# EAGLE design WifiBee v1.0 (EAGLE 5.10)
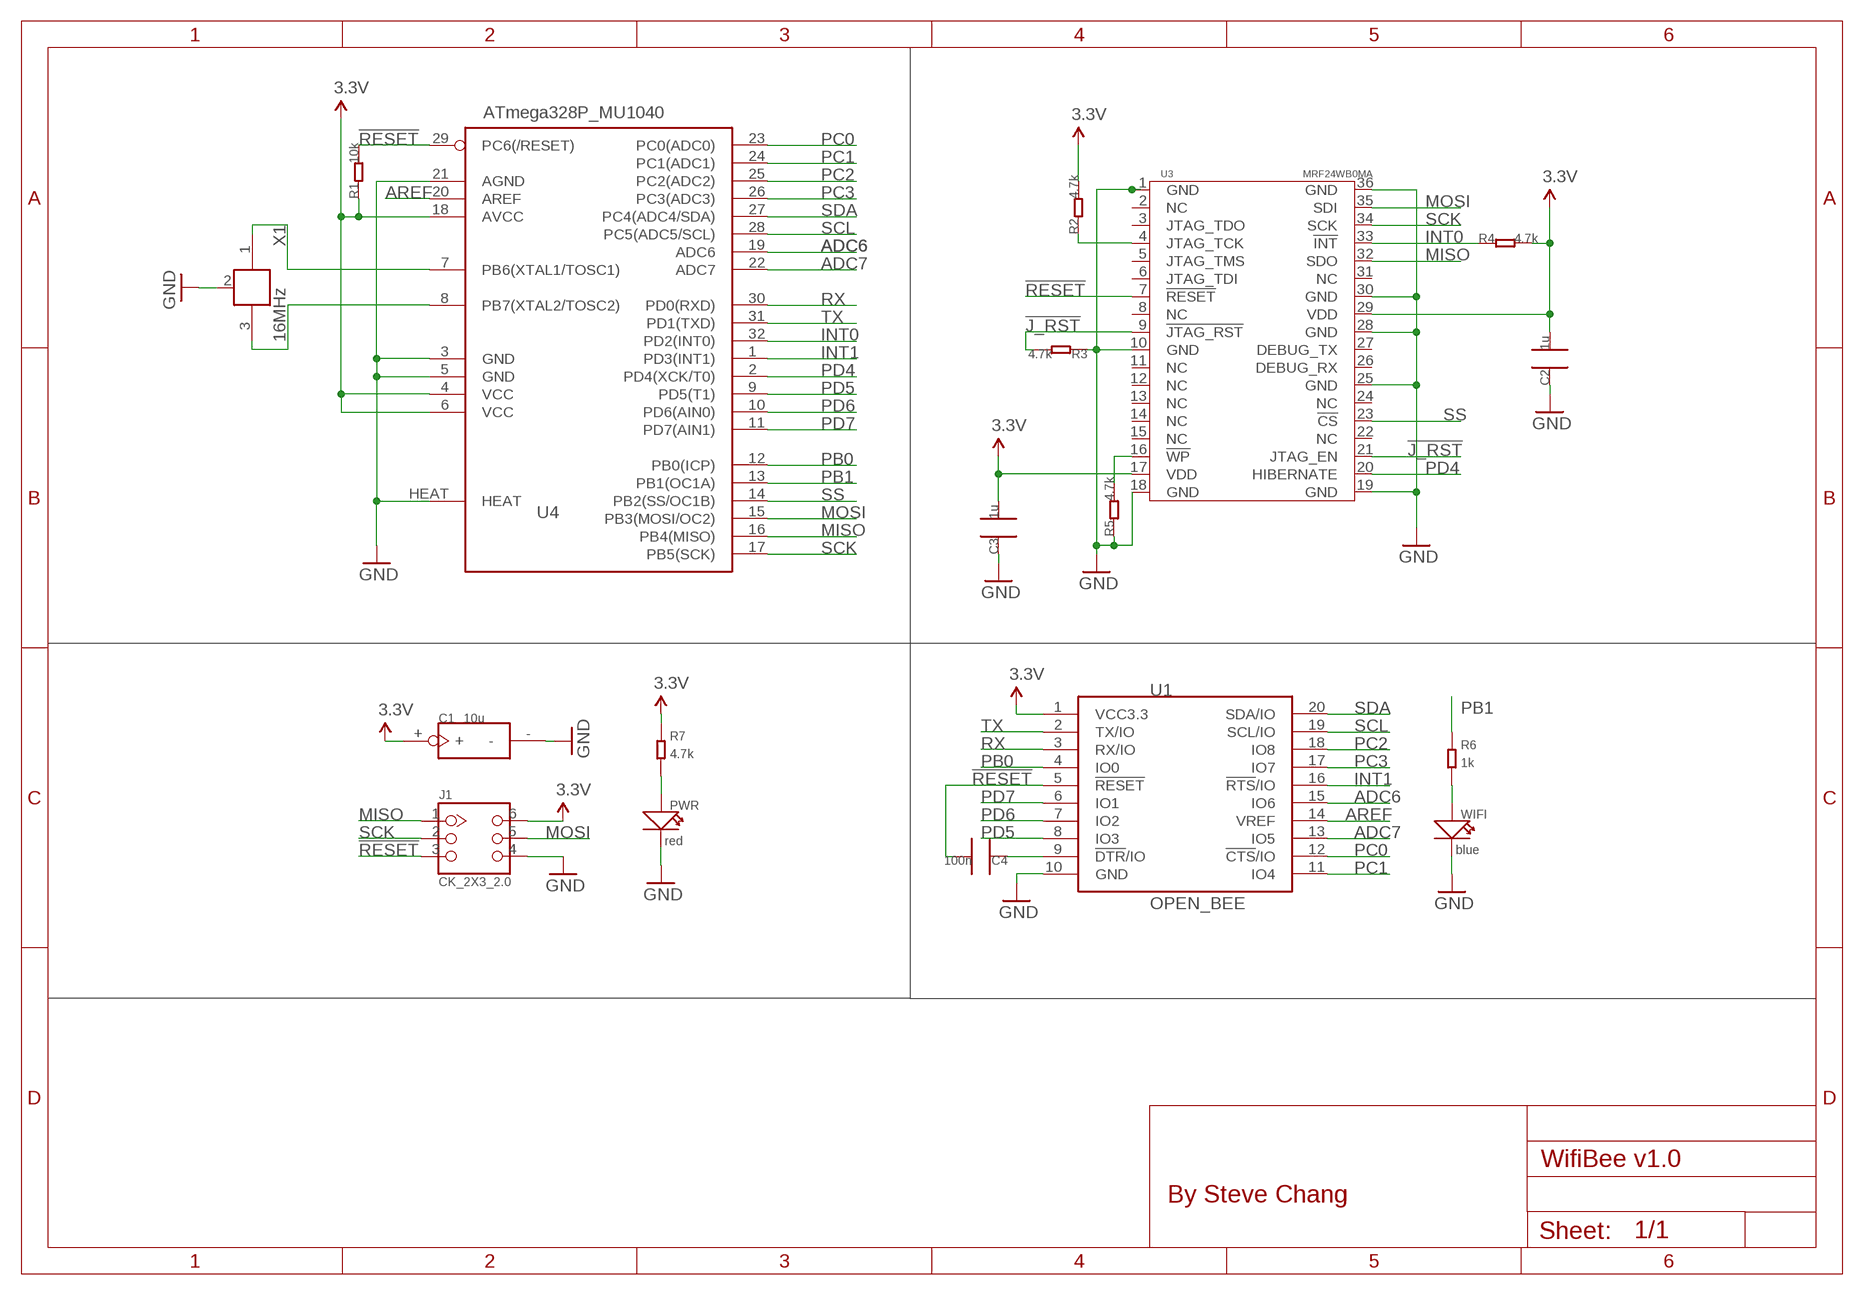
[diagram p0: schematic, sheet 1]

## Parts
C1  10u  C_TAN_B  [C_TAN_3X3.5]
C2  1u  C0603  [0603]
C3  1u  C0603  [0603]
C4  100n  C0603  [0603]
J1  CK_2X3_2.0  [CK_2X3_2.0]
PWR  red  LED0603_DD  [LED0603]
R1  10k  R0603  [0603]
R2  4.7k  R0603  [0603]
R3  4.7k  R0603  [0603]
R4  4.7k  R0603  [0603]
R5  4.7k  R0603  [0603]
R6  1k  R0603  [0603]
R7  4.7k  R0603  [0603]
U1  OPEN_BEE  OPEN_BEE_SMD  [XBEE_EXT_SMD]
U3  MRF24WB0MA  WIFI_SMT  [MRF24WB0MA]
U4  ATmega328P_MU1040  MEGA8_MLF32X  [MLF32X]
WIFI  blue  LED0603_DD  [LED0603]
X1  16MHz  XTAL_NCVER  [XTAL_3X2]

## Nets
3.3V: C1.+ C2.2 C3.2 J1.6 R1.1 R2.2 R4.2 R7.1 U1.1(VCC3.3) U3.17(VDD) U3.29(VDD) U4.4(VCC) U4.6(VCC) U4.18(AVCC)
!J_RST: R3.2 U3.9(!JTAG_RST) U3.21(JTAG_EN)
!RESET: C4.2 J1.3 R1.2 U1.5(!RESET) U3.7(!RESET) U4.29(PC6(/RESET))
ADC6: U1.15(IO6) U4.19(ADC6)
ADC7: U1.13(IO5) U4.22(ADC7)
AREF: U1.14(VREF) U4.20(AREF)
GND: C1.- C2.1 C3.1 J1.4 PWR.2(-) R3.1 R5.1 U1.10(GND) U3.1(GND) U3.10(GND) U3.18(GND) U3.19(GND) U3.25(GND) U3.28(GND) U3.30(GND) U3.36(GND) U4.3(GND) U4.5(GND) U4.21(AGND) U4.HEAT WIFI.2(-) X1.2(GND)
INT0: R4.1 U3.33(!INT) U4.32(PD2(INT0))
INT1: U1.16(!RTS!/IO) U4.1(PD3(INT1))
MISO: J1.1 U3.32(SDO) U4.16(PB4(MISO))
MOSI: J1.5 U3.35(SDI) U4.15(PB3(MOSI/OC2))
N$1: C4.1 U1.9(!DTR!/IO)
N$3: R5.2 U3.16(!WP)
N$5: R2.1 U3.4(JTAG_TCK)
N$7: R6.2 WIFI.1(+)
N$8: PWR.1(+) R7.2
N$11: U4.7(PB6(XTAL1/TOSC1)) X1.1
N$13: U4.8(PB7(XTAL2/TOSC2)) X1.3
PB0: U1.4(IO0) U4.12(PB0(ICP))
PB1: R6.1 U4.13(PB1(OC1A))
PC0: U1.12(!CTS!/IO) U4.23(PC0(ADC0))
PC1: U1.11(IO4) U4.24(PC1(ADC1))
PC2: U1.18(IO8) U4.25(PC2(ADC2))
PC3: U1.17(IO7) U4.26(PC3(ADC3))
PD4: U3.20(HIBERNATE) U4.2(PD4(XCK/T0))
PD5: U1.8(IO3) U4.9(PD5(T1))
PD6: U1.7(IO2) U4.10(PD6(AIN0))
PD7: U1.6(IO1) U4.11(PD7(AIN1))
RX: U1.3(RX/IO) U4.30(PD0(RXD))
SCK: J1.2 U3.34(SCK) U4.17(PB5(SCK))
SCL: U1.19(SCL/IO) U4.28(PC5(ADC5/SCL))
SDA: U1.20(SDA/IO) U4.27(PC4(ADC4/SDA))
SS: U3.23(!CS) U4.14(PB2(SS/OC1B))
TX: U1.2(TX/IO) U4.31(PD1(TXD))
Unconnected: U3.2(NC) U3.3(JTAG_TDO) U3.5(JTAG_TMS) U3.6(JTAG_TDI) U3.8(NC) U3.11(NC) U3.12(NC) U3.13(NC) U3.14(NC) U3.15(NC) U3.22(NC) U3.24(NC) U3.26(DEBUG_RX) U3.27(DEBUG_TX) U3.31(NC)

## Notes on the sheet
- By Steve Chang

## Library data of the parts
C1 = CPT_SMD:C_TAN
C2-C4 = CPT_SMD:C0603; C0603: 100N
J1 = CONNECTER:CK_2X3
PWR WIFI = CPT_SMD:LED0603
R1-R7 = CPT_SMD:R0603
U1 = EXT_moudle:OPEN_BEE
U3 = EXT_moudle:WIFI
U4 = ICs_v54:MEGA8
X1 = CPT_SMD:XTAL_NC

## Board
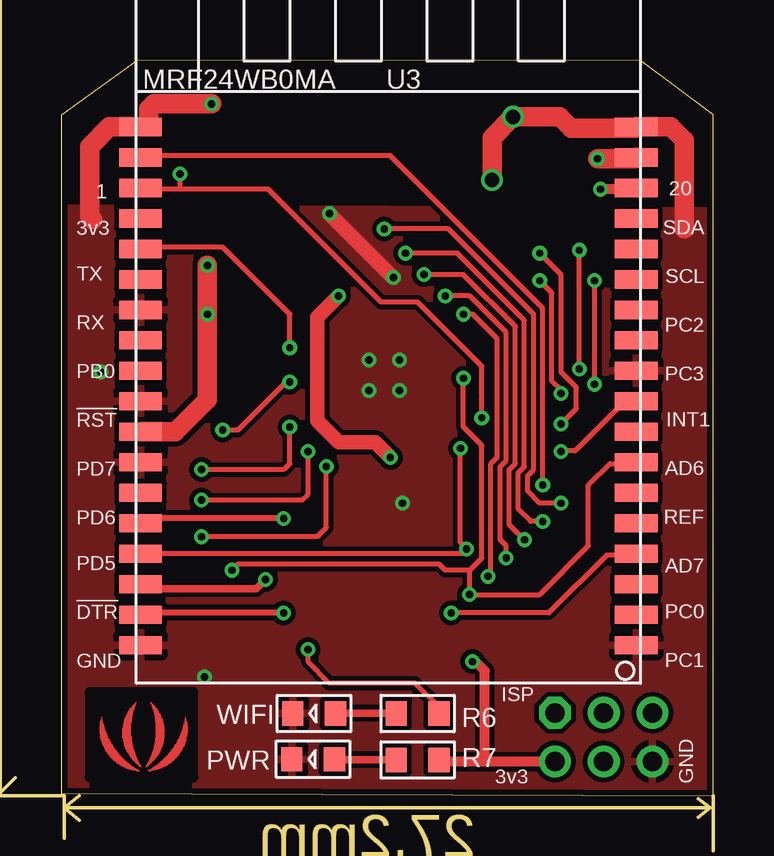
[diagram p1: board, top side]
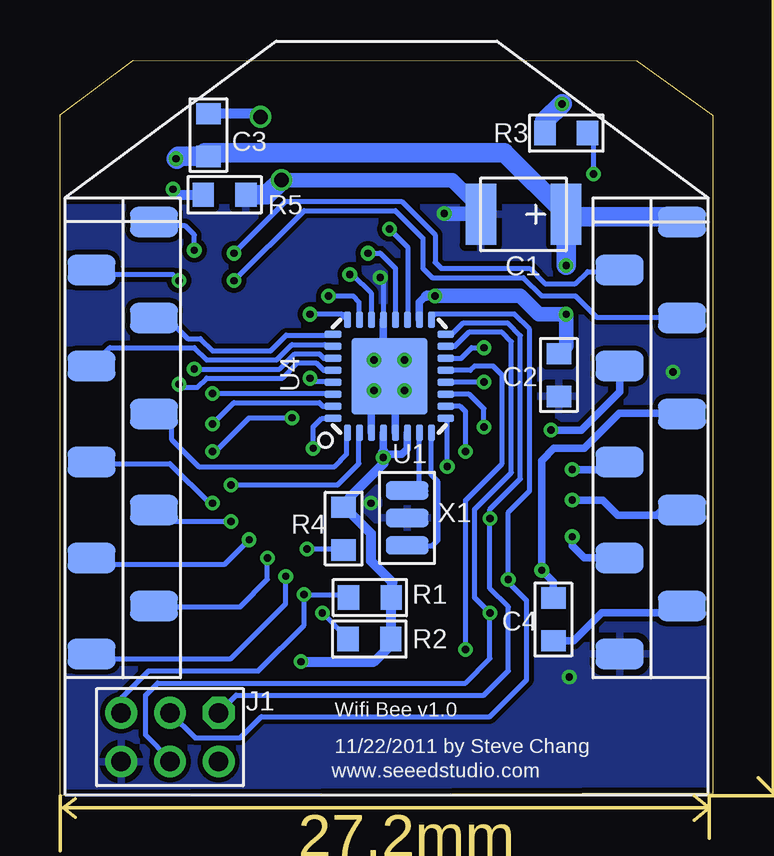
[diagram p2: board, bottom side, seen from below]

Size 27.18 x 30.66 mm. Coordinates in mm from the lower left corner, seen from the top.
Outline: 24.14,30.66 27.18,28.37 27.18,0 0,0.1 0,28.35 3.15,30.63 3.15,30.63 24.14,30.66
Outline: 24.14,30.66 24.14,30.66
Copper layers (1*16): Top 0.035mm / dielectric 1.5mm / Bottom 0.035mm
Design rules "SeeedStudio_rule_no_angle_090911": minimum track width 6mil, minimum drill 12mil, track to track 6mil, track to pad 6mil, pad to pad 6mil, via to via 6mil, smd to smd 0mil, copper to edge 10mil, drill to drill 10mil, minimum pad ring 10mil, minimum via ring 6mil, stop-mask expansion 2mil, vias tented up to drill 100mil, thermal gap 10mil
tRestrict: area 1.2,0.8 to 5.5,4.3
Milling: 26 lines

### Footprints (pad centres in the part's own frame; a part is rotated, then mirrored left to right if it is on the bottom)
C_TAN_3X3.5 = smd 2.54 x 1.27: + 0,1.778; - 0,-1.778
0603 = smd 0.889 x 1.016: 1 -0.889,0; 2 0.889,0
CK_2X3_2.0 = drill 0.813 pad 1.27 octagon: 1 -1.016,2.032 | drill 0.813 pad 1.27 round: 2 -1.016,0; 3 -1.016,-2.032; 4 1.016,-2.032; 5 1.016,0; 6 1.016,2.032
LED0603 = smd 0.889 x 1.016: 1 -0.889,0; 2 0.889,0
XBEE_EXT_SMD = smd 2 x 1.27: 1 12.3,9; 2 9.7,7; 3 12.3,5; 4 9.7,3; 5 12.3,1; 6 9.7,-1; 7 12.3,-3; 8 9.7,-5; 9 12.3,-7; 10 9.7,-9; 11 -12.3,-9; 12 -9.7,-7; 13 -12.3,-5; 14 -9.7,-3; 15 -12.3,-1; 16 -9.7,1; 17 -12.3,3; 18 -9.7,5; 19 -12.3,7; 20 -9.7,9
MRF24WB0MA = smd 1.778 x 0.762: 1 -10.624,23.695; 2 -10.624,22.425; 3 -10.624,21.155; 4 -10.624,19.885; 5 -10.624,18.615; 6 -10.624,17.345; 7 -10.624,16.075; 8 -10.624,14.805; 9 -10.624,13.535; 10 -10.624,12.265; 11 -10.624,10.995; 12 -10.624,9.725; 13 -10.624,8.455; 14 -10.624,7.185; 15 -10.624,5.915; 16 -10.624,4.645; 17 -10.624,3.375; 18 -10.624,2.105; 19 10.034,2.105; 20 10.034,3.375; 21 10.034,4.645; 22 10.034,5.915; 23 10.034,7.185; 24 10.034,8.455; 25 10.034,9.725; 26 10.034,10.995; 27 10.034,12.265; 28 10.034,13.535; 29 10.034,14.805; 30 10.034,16.075; 31 10.034,17.345; 32 10.034,18.615; 33 10.034,19.885; 34 10.034,21.155; 35 10.034,22.425; 36 10.034,23.695
MLF32X = smd 0.7 x 0.3: 1 -2.35,1.75; 2 -2.35,1.25; 3 -2.35,0.75; 4 -2.35,0.25; 5 -2.35,-0.25; 6 -2.35,-0.75; 7 -2.35,-1.25; 8 -2.35,-1.75; 17 2.35,-1.75; 18 2.35,-1.25; 19 2.35,-0.75; 20 2.35,-0.25; 21 2.35,0.25; 22 2.35,0.75; 23 2.35,1.25; 24 2.35,1.75 | smd 0.3 x 0.7: 9 -1.75,-2.35; 10 -1.25,-2.35; 11 -0.75,-2.35; 12 -0.25,-2.35; 13 0.25,-2.35; 14 0.75,-2.35; 15 1.25,-2.35; 16 1.75,-2.35; 25 1.75,2.35; 26 1.25,2.35; 27 0.75,2.35; 28 0.25,2.35; 29 -0.25,2.35; 30 -0.75,2.35; 31 -1.25,2.35; 32 -1.75,2.35 | smd 3.175 x 3.175: HEAT 0,0
XTAL_3X2 = smd 0.762 x 1.778: 1 -1.143,0; 2 0,0; 3 1.143,0

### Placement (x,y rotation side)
C1  7.88,24.23 270 bottom
C2  6.41,17.53 90 bottom
C3  21.01,27.53 270 bottom
C4  6.63,7.35 90 bottom
J1  22.61,2.44 270 bottom
PWR  10.5,1.52 180 top
R1  14.28,8.26 180 bottom
R2  14.3,6.53 0 bottom
R3  6.1,27.61 0 bottom
R4  15.37,11.13 90 bottom
R5  20.33,25.04 180 bottom
R6  14.86,3.43 180 top
R7  14.86,1.5 180 top
U1  13.57,14.91 0 bottom
U3  13.35,29.97 180 top
U4  13.47,17.48 90 bottom
U$1  [LOGO_COPPER_150X124]  3.43,2.16 0 top
WIFI  10.54,3.43 180 top
X1  12.73,11.58 270 bottom

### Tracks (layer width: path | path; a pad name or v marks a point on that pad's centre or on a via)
3.3V  (via drill 0.3)
  Top 0.305: 15.82,1.43 R7.1
  Top 0.406: v17.15,5.59 17.28,5.59 17.66,5.21 17.66,1.68 | 17.91,1.43 17.66,1.68 | J1.6 17.91,1.43 | 17.91,1.43 15.82,1.43 | 17.66,1.68 17.66,1.65 17.45,1.45
  Top 0.61: v11.56,20.83 10.67,19.94 10.67,15.62 11.56,14.73 13.09,14.73 v13.72,14.1
  Top 0.813: v22.36,26.54 23.92,26.54 U3.17 | v6.1,22.1 v6.1,20.07 6.1,16.51 4.75,15.16 U3.29
  Bottom 0.305: 11.94,20.83 12.22,20.55 U4.18 | U4.6 12.72,14.47 12.96,14.22 13.59,14.22 13.72,14.35 U4.4
  Bottom 0.406: v11.56,20.83 11.94,20.83 | 13.72,14.35 v13.72,14.1 13.72,13.84 15.12,12.45 15.12,12.27 R4.2 15.33,12.02 14.23,10.92 14.23,9.78 13.34,8.89 13.34,8.31 R1.1 13.39,6.55 R2.2 13.41,6.28 14.1,5.59 v17.15,5.59
  Bottom 0.61: v11.56,20.83 8.01,20.83 7.24,20.07 v6.1,20.07 6.1,18.73 C2.2
  Bottom 0.813: 22.33,26.51 v22.36,26.54 22.26,26.64 C3.2 21.17,26.8 8.67,26.8 C1.+ | C1.+ 6,24.13 1.5,24.13 U1.1 | v6.1,22.1 C1.+
!J_RST  (via drill 0.3)
  Top 0.152: U3.9 23.77,16.64 | 3.37,25.27 U3.21
  Top 0.203: v17.53,15.75 17.53,17.91 14.86,20.57 13.34,20.57 8.64,25.27 4.83,25.27 | 4.83,25.27 3.37,25.27 | v4.96,25.91 4.96,25.4 4.83,25.27 | U3.9 23.48,16.44 21.42,14.38 20.86,14.38 v20.83,14.35
  Bottom 0.152: 4.96,27.36 R3.2
  Bottom 0.203: v17.53,15.75 19.31,15.75 20.71,14.35 v20.83,14.35 | v4.96,25.91 4.96,27.36
!RESET  (via drill 0.3)
  Top 0.152: 23.92,13.84 U3.7
  Top 0.203: 23.92,13.84 22.86,13.84 21.98,12.95 21.98,10.41 19.94,8.38 v17.02,8.38 17.02,9.4 | v16.77,17.4 16.77,15.37 17.53,14.61 17.53,9.91 17.02,9.4 | v7.12,9.4 7.37,9.65 15.75,9.65 16.01,9.4 17.02,9.4
  Bottom 0.152: 15.86,17.27 U4.29 | 15.3,8.38 R1.2
  Bottom 0.203: 15.86,17.27 16.64,17.27 v16.77,17.4 | J1.3 24.64,4.06 23.5,5.21 18.93,5.21 17.02,7.11 v17.02,8.38 15.3,8.38
  Bottom 0.305: C4.2 6.63,8.91 v7.12,9.4 7.12,13.97 6.61,14.48 5.34,14.48 3.88,15.93 1.3,15.93 U1.5
ADC6  (via drill 0.3)
  Top 0.203: v20.83,12.19 19.94,12.19 19.44,12.7 19.44,13.34 19.69,13.59 19.69,20.07 16.13,23.62 v13.47,23.62
  Bottom 0.152: U1.15 25.81,13.84
  Bottom 0.203: v20.83,12.19 20.96,12.19 22.61,13.84 25.81,13.84 | v13.47,23.62 12.71,22.86 12.71,19.84
  Bottom 0.254: 12.71,19.84 U4.19
ADC7  (via drill 0.3)
  Top 0.203: v19.31,10.67 18.67,11.3 18.67,13.59 18.93,13.84 18.93,19.56 16.77,21.72 v15.12,21.72
  Bottom 0.152: 14.23,19.84 U4.22
  Bottom 0.203: v15.12,21.72 14.99,21.72 14.23,20.95 14.23,19.84 | v19.31,10.67 20.32,9.65 25.64,9.65 25.64,9.67 U1.13
AREF  (via drill 0.3)
  Top 0.203: v20.07,11.43 19.56,11.43 19.05,11.94 19.05,13.46 19.31,13.72 19.31,19.81 16.52,22.61 v14.36,22.61
  Bottom 0.152: U4.20
  Bottom 0.203: 22.8,11.43 23.38,11.43 | v14.36,22.61 13.85,22.61 13.21,21.97 U4.20 | 22.8,11.43 v20.07,11.43 | U1.14 22.8,11.43
GND  (via drill 0.3, 0.6)
  Top 0.406: 3.66,27.87 U3.19
  Top 0.61: v11.18,24.26 v13.85,21.59
  Top 0.813: 1.32,24 1.19,24.13 1.19,27.05 2.01,27.87 3.66,27.87 3.66,28.63 3.86,28.83 v6.27,28.83 | 25.96,23.62 25.96,27.3 25.4,27.87 U3.18 23.92,27.81 21.26,27.81 20.78,28.29 v18.83,28.29 17.96,27.42 v17.96,25.65
  Bottom 0.152: 9.94,24.51 C1.-
  Bottom 0.203: U4.21 13.72,21.46 v13.85,21.59
  Bottom 0.305: U4.21 13.72,18.8 | 13.72,18.8 13.59,18.67 | U4.5 13.22,17.23 U4.HEAT | U4.3 14.22,16.73 U4.HEAT | U4.HEAT 13.47,17.78 | v14.1,16.89 14.06,16.89 U4.HEAT | 13.72,18.8 13.72,17.73 U4.HEAT
  Bottom 0.406: C3.1 18.96,28.42 v18.83,28.29
  Bottom 0.61: v11.18,24.26 9.69,24.26 C1.- | 9.94,24.51 9.94,24.75 10.85,25.65 v17.96,25.65
  Bottom 0.813: R3.1 6.99,28.12 v6.27,28.83 | R5.1 18.57,25.04 v17.96,25.65
  other vias: 14.1,18.16 5.97,4.95 14.23,12.19 1.66,17.65 12.83,18.16 12.83,16.89
  pour Top (isolate 0.203): 26.93,24.38 0.39,24.51 0.39,0.13 26.93,0
  pour Bottom (isolate 0.203): 26.93,24.51 0.39,24.51 0.39,0.13 26.93,0.13
INT0  (via drill 0.3)
  Top 0.203: v16.64,14.48 16.64,10.54 v16.9,10.29 16.7,10.09 U3.33
  Bottom 0.152: 15.42,10.29 R4.1
  Bottom 0.203: U4.32 16.28,15.73 16.64,15.37 v16.64,14.48 | v16.9,10.29 15.42,10.29
INT1
  Bottom 0.152: 15.24,15.1 U4.1
  Bottom 0.203: 15.24,15.1 15.24,14.22 15.75,13.72 21.42,13.72 22.54,14.83 22.54,15.75 22.61,15.82 23.19,15.82 U1.16
MISO  (via drill 0.3)
  Top 0.254: 3.38,11.43 U3.32 3.51,11.56 v9.28,11.56
  Bottom 0.203: U4.16 10.86,19.24 10.42,19.68 8.51,19.68 8.01,19.18 8.01,13.21 9.28,11.94 v9.28,11.56 9.28,8.64 8.51,7.87 8.51,5.21 9.53,4.19 19.85,4.19 J1.1
  Bottom 0.254: U4.16
MOSI  (via drill 0.3)
  Top 0.254: v9.28,7.62 3.38,7.62 U3.35
  Bottom 0.203: U4.15 10.74,18.73 10.16,19.3 8.77,19.3 8.39,18.92 8.39,13.46 9.91,11.94 9.91,8.26 v9.28,7.62 9.28,5.71 10.29,4.7 23.12,4.7 23.63,4.19 23.63,2.54 22.61,1.52 J1.5
N$1
  Bottom 0.305: C4.1 5.79,6.46 4.62,7.62 1.56,7.62 U1.9
N$3  (via drill 0.3)
  Top 0.406: v22.48,25.27 23.92,25.27 U3.16
  Bottom 0.406: R5.2 22.26,25.04 v22.48,25.27
N$5  (via drill 0.3)
  Top 0.152: U3.4 23.92,10.03
  Top 0.203: v16.26,7.62 20.32,7.62 22.74,10.03 23.92,10.03
  Bottom 0.203: v16.26,7.62 15.3,6.66 15.3,6.63 R2.1
N$7
  Top 0.305: R6.2 WIFI.1
N$8
  Top 0.305: R7.2 11.41,1.5 PWR.1
N$11
  Bottom 0.203: U4.7 12.22,12.97 11.94,12.7 12.71,12.7 X1.1
N$13
  Bottom 0.152: X1.3 12.71,10.41
  Bottom 0.203: U4.8 11.72,13.36 11.44,13.08 11.44,10.67 11.69,10.41 12.71,10.41
PB0  (via drill 0.3)
  Top 0.203: v9.53,17.25 9.38,17.25 7.37,15.24 v6.74,15.24
  Bottom 0.152: U4.12 11.1,17.25
  Bottom 0.203: 11.1,17.25 v9.53,17.25
  Bottom 0.305: v6.74,15.24 5.47,15.24 3.87,16.84 U1.4
PB1  (via drill 0.3)
  Top 0.152: R6.1 15.75,3.68
  Top 0.203: 15.75,3.68 14.74,4.7 11.18,4.7 10.29,5.59 v10.29,6.1
  Top 0.254: R6.1
  Bottom 0.203: U4.13 10.09,17.73 9.91,17.91 9.15,17.91 8.77,17.53 8.77,13.84 10.29,12.32 v10.29,6.1
PC0  (via drill 0.3)
  Top 0.203: v18.55,9.91 18.55,10.41 18.29,10.67 18.29,13.72 18.55,13.97 18.55,19.3 17.02,20.83 v16.01,20.83
  Bottom 0.152: U1.12 23.24,7.87
  Bottom 0.203: v16.01,20.83 14.99,20.83 14.74,20.57 14.74,19.85 | v18.55,9.91 18.55,9.02 19.69,7.87 23.24,7.87
  Bottom 0.254: 14.74,19.85 U4.23
PC1  (via drill 0.3)
  Top 0.203: v17.79,9.14 17.91,9.27 17.91,13.84 18.17,14.1 18.17,19.05 17.15,20.07 v16.77,20.07
  Bottom 0.152: v16.77,20.07 15.45,20.07
  Bottom 0.203: v17.79,9.14 17.79,8 20.07,5.71 25.68,5.71 U1.11 | 15.45,20.07 16.8,20.07 | 15.45,20.07 U4.24 | 15.45,20.07 15.22,20.07 15.17,20.02
PC2
  Bottom 0.152: 15.85,19.2 U4.25
  Bottom 0.203: 15.85,19.2 17.77,19.2 18.42,18.54 20.83,18.54 21.34,19.05 21.88,19.05 22.73,19.91 U1.18
PC3
  Bottom 0.203: U4.26 16.09,18.73 16.16,18.8 17.53,18.8 18.17,18.16 21.09,18.16 21.59,18.67 25.11,18.67 U1.17
PD4  (via drill 0.3)
  Top 0.152: 3.38,26.67 U3.20
  Top 0.203: v20.07,12.95 20.07,20.32 13.72,26.67 3.38,26.67
  Bottom 0.152: 14.74,15.11 U4.2
  Bottom 0.203: 14.74,15.11 14.74,13.84 15.63,12.95 v20.07,12.95
PD5  (via drill 0.3)
  Top 0.203: v11.05,13.72 11.05,11.18 10.67,10.79 v5.85,10.79
  Bottom 0.152: 11.05,15.67 U4.9
  Bottom 0.203: v11.05,13.72 11.05,15.67
  Bottom 0.305: U1.8 5.34,9.91 5.85,10.41 v5.85,10.79
PD6  (via drill 0.3)
  Top 0.203: v10.29,14.35 10.29,12.57 10.04,12.32 v5.85,12.32
  Bottom 0.203: U4.10 10.52,16.23 10.29,16 v10.29,14.35
  Bottom 0.254: 2,12.06 2.38,11.68
  Bottom 0.305: v5.85,12.32 4.58,12.32 3.94,11.68 1.62,11.68 | U1.7 1.5,11.68 1.62,11.68 | 1.62,11.68 2,12.06
PD7  (via drill 0.3)
  Top 0.203: v9.53,15.37 9.53,13.84 9.28,13.59 v5.85,13.59
  Bottom 0.203: U4.11 10.13,16.73 9.53,16.13 v9.53,15.37
  Bottom 0.305: v5.85,13.59 3.73,13.59 3.73,13.77 U1.6
RX  (via drill 0.3, 0.3 pad 0.61)
  Top 0.203: v20.83,16.76 20.83,16.89 20.45,17.27 20.45,20.95 v19.94,21.46
  Bottom 0.152: 15.85,16.76 U4.30 | 1.3,19.93 U1.3
  Bottom 0.203: v20.83,16.76 15.85,16.76 | v19.94,21.46 17.02,24.38 13.21,24.38 12.07,23.24 12.07,21.97 11.69,21.59 7.88,21.59 7.12,20.83 5.72,20.83 4.83,19.93 1.3,19.93
SCK  (via drill 0.3)
  Top 0.305: 3.51,9.02 U3.34 3.49,8.64 8.13,8.64 v8.51,9.02
  Bottom 0.203: 11.72,19.91 11.56,20.07 8.26,20.07 7.62,19.43 7.62,12.7 8.51,11.81 v8.51,9.02 8.51,8.89 7.75,8.13 7.75,4.83 9.28,3.3 18.8,3.3 19.69,2.41 21.57,2.41 J1.2
  Bottom 0.254: 11.72,19.91 U4.17
SCL  (via drill 0.3)
  Top 0.203: v22.23,17.14 v22.23,21.46
  Bottom 0.203: U4.28 16.21,17.73 16.52,18.03 17.28,18.03 17.91,17.4 21.09,17.4 21.47,17.02 22.1,17.02 v22.23,17.14 | v22.23,21.46 22.48,21.72 25.68,21.72 U1.19
SDA  (via drill 0.3)
  Top 0.203: v21.59,17.78 v21.59,22.73
  Bottom 0.203: U4.27 16.2,18.23 16.39,18.41 17.4,18.41 18.04,17.78 v21.59,17.78 | v21.59,22.73 21.59,23.37 21.98,23.75 23.37,23.75 | 23.37,23.75 23.61,23.75 | U1.20 23.27,23.85 23.37,23.75
SS  (via drill 0.3)
  Top 0.203: 3.38,22.86 6.74,22.86 9.53,20.07 v9.53,18.67
  Top 0.254: 3.38,22.86 U3.23
  Bottom 0.203: U4.14 10.48,18.23 10.04,18.67 v9.53,18.67
TX  (via drill 0.3, 0.3 pad 0.61)
  Top 0.203: v19.94,22.61 20.83,21.72 20.83,17.65 21.47,17.02 21.47,16.13 v20.83,15.49
  Bottom 0.152: 3.94,21.84 U1.2
  Bottom 0.203: U4.31 16.24,16.23 16.39,16.38 19.94,16.38 v20.83,15.49 | v19.94,22.61 17.79,24.77 12.96,24.77 11.56,23.37 11.56,22.23 11.31,21.97 7.62,21.97 6.99,21.34 5.72,21.34 5.21,21.84 3.94,21.84

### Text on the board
tPlace: 1 | 20 | SDA | 3v3 | SCL | TX | PC2 | RX | PC3 | PB0 | INT1 | !RST | AD6 | PD7 | REF | PD6 | AD7 | PD5 | PC0 | !DTR | PC1 | GND | ISP | 3v3 | GND
bPlace: Wifi Bee v1.0 | 11/22/2011 by Steve Chang | www.seeedstudio.com
Milling: 21.0mm | 35.7mm | 27.2mm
